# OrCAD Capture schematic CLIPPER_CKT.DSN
size A
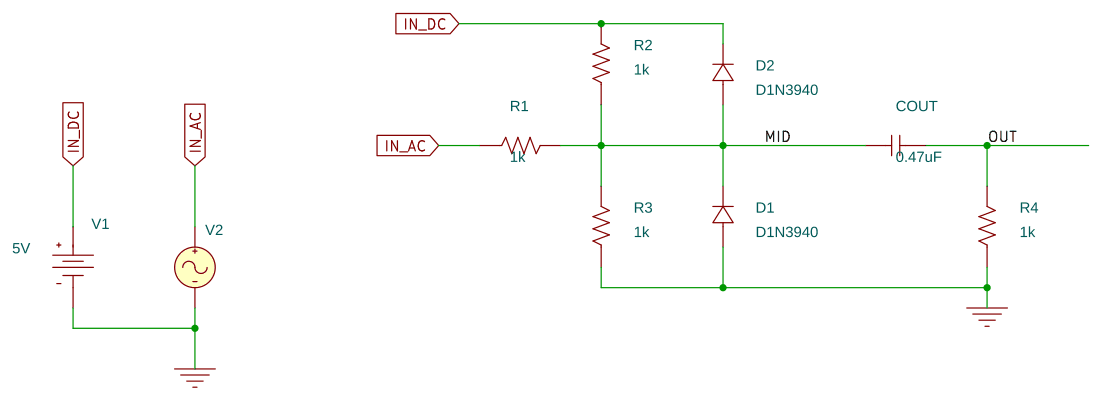
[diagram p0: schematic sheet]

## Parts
COUT  0.47uF  [CK05]
D1  D1N3940  [dax1375x070034]
D2  D1N3940  [dax1375x070034]
R1  1k  [RC05]
R2  1k  [RC05]
R3  1k  [RC05]
R4  1k  [RC05]
V1  VDC
V2  VAC

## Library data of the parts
COUT = C
D1 D2 = D1N3940
R1-R4 = R
V1 = VDC: DC: 5V
V2 = VAC

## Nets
0: D1.1 R3.1 R4.1 V1.1(-) V2.2(-)
IN_AC: R1.1 V2.1(+)
IN_DC: D2.2 R2.2 V1.0(+)
MID: COUT.1 D1.2 D2.1 R1.2 R2.1 R3.2
OUT: COUT.2 R4.2
